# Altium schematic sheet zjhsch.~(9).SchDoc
size A4
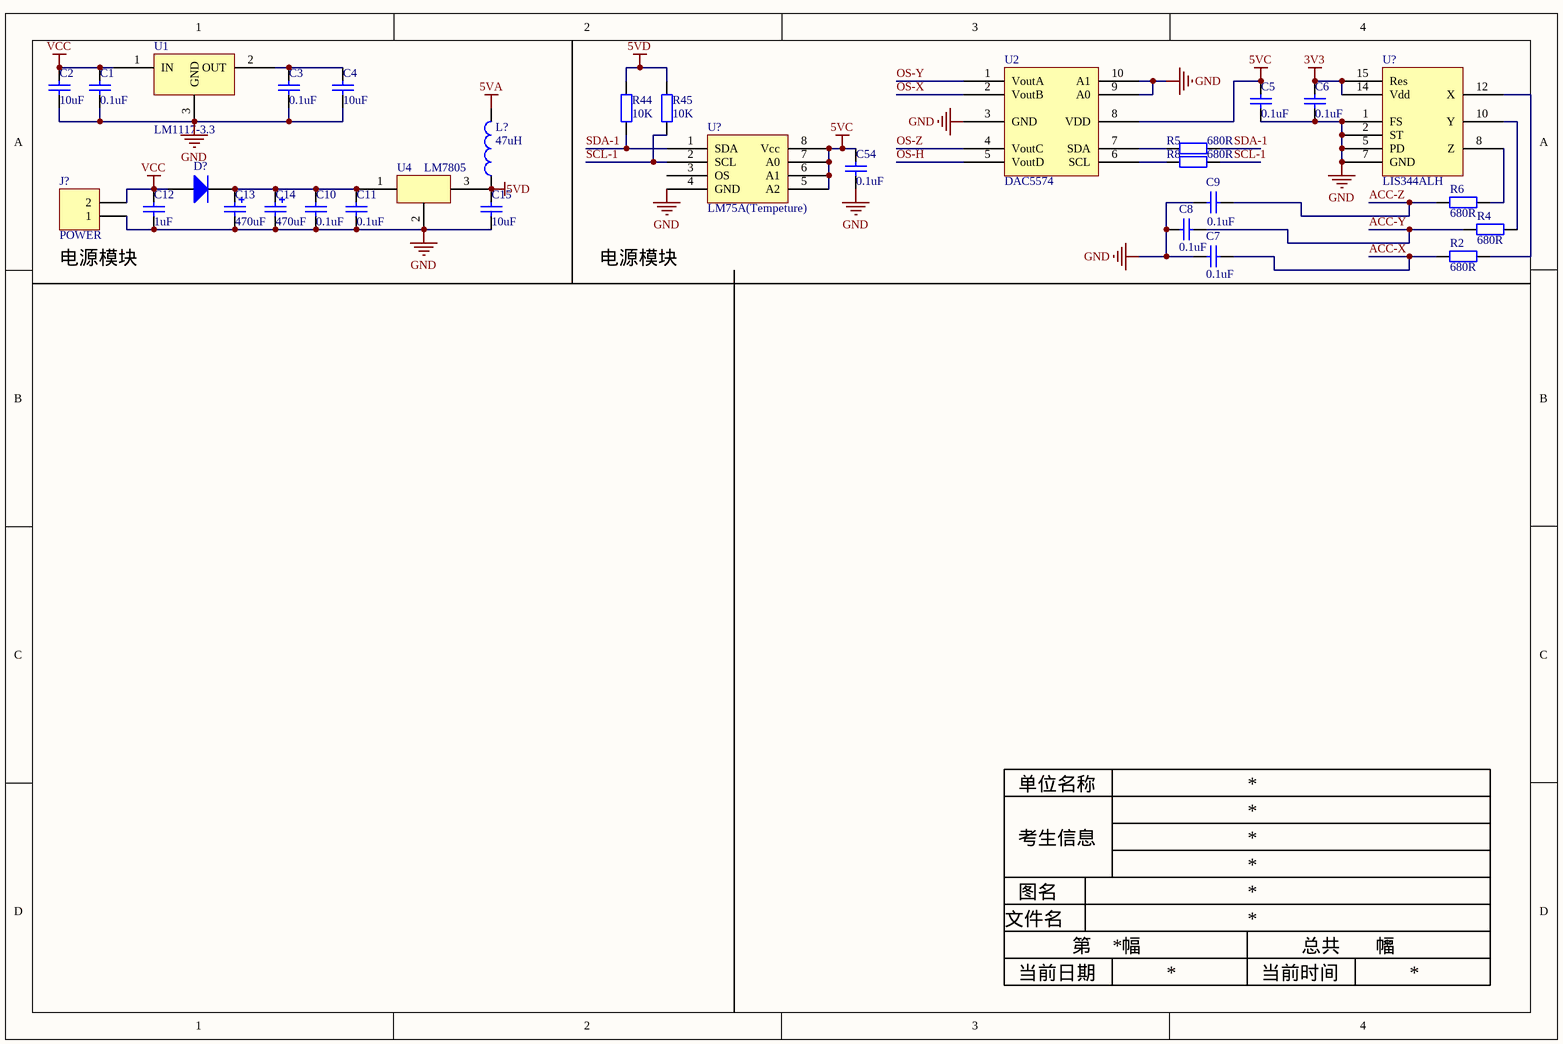
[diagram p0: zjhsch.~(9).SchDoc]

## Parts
(Parts that share a designator on the sheet are numbered #1, #2 ... from top to bottom, then left to right.)
C1  value 0.1uF  [RAD-0.3]  (hidden comment: Cap)
C2  value 10uF  [RAD-0.3]  (hidden comment: Cap)
C3  value 0.1uF  [RAD-0.3]  (hidden comment: Cap)
C4  value 10uF  [RAD-0.3]  (hidden comment: Cap)
C5  value 0.1uF  [RAD-0.3]  (hidden comment: Cap)
C6  value 0.1uF  [RAD-0.3]  (hidden comment: Cap)
C7  value 0.1uF  [RAD-0.3]  (hidden comment: Cap)
C8  value 0.1uF  [RAD-0.3]  (hidden comment: Cap)
C9  value 0.1uF  [RAD-0.3]  (hidden comment: Cap)
C10  value 0.1uF  [RAD-0.3]  (hidden comment: Cap)
C11  value 0.1uF  [RAD-0.3]  (hidden comment: Cap)
C12  value 1uF  [RAD-0.3]  (hidden comment: Cap)
C13  value 470uF  [POLAR0.8]  (hidden comment: Cap Pol2)
C14  value 470uF  [POLAR0.8]  (hidden comment: Cap Pol2)
C15  value 10uF  [RAD-0.3]  (hidden comment: Cap)
C54  value 0.1uF  [RAD-0.3]  (hidden comment: Cap)
D?  Diode  [SMC]  (value not drawn)
J?  POWER  [HDR1X2]
L?  47uH  [DIODE_SMC]
R2  680R  [R0603]
R4  680R  [R0603]
R5  680R  [R0603]
R6  680R  [R0603]
R8  680R  [R0603]
R44  10K  [1608[0603]]
R45  10K  [1608[0603]]
U1  LM1117-3.3  [LM1117-3.3]
U2  DAC5574
U4  LM7805  [TO-220AB]
U?#1  LIS344ALH  [LIS344ALH(Acc)]
U?#2  LM75A(Tempeture)  [LM75A]

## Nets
3V3: C6.2 U?#1.14(Vdd) U?#1.15(Res)
5VA: L?.2
5VC: C5.2 C54.2 U2.8(VDD) U?#2.5(A2) U?#2.6(A1) U?#2.7(A0) U?#2.8(Vcc)
5VD: C15.2 L?.1 R44.2 R45.2 U4.3
GND: C1.1 C2.1 C3.1 C4.1 C5.1 C6.1 C7.2 C8.2 C9.2 C10.1 C11.1 C12.1 C13.2 C14.2 C15.1 C54.1 J?.1 U1.3(GND) U2.3(GND) U2.9(A0) U2.10(A1) U4.2 U?#1.1(FS) U?#1.2(ST) U?#1.5(PD) U?#1.7(GND) U?#2.4(GND)
VCC: C1.2 C2.2 C12.2 D?.1(A) J?.2 U1.1(IN)
ACC-X: C7.1 R2.2
ACC-Y: C8.1 R4.2
ACC-Z: C9.1 R6.2
OS-H: U2.5(VoutD)
OS-X: U2.2(VoutB)
OS-Y: U2.1(VoutA)
OS-Z: U2.4(VoutC)
SCL-1: R8.2 R45.1 U?#2.2(SCL)
SDA-1: R5.2 R44.1 U?#2.1(SDA)
NetC3_2: C3.2 C4.2 U1.2(OUT)
NetC10_2: C10.2 C11.2 C13.1 C14.1 D?.2(K) U4.1
NetR2_1: R2.1 U?#1.12(X)
NetR4_1: R4.1 U?#1.10(Y)
NetR5_1: R5.1 U2.7(SDA)
NetR6_1: R6.1 U?#1.8(Z)
NetR8_1: R8.1 U2.6(SCL)

Not connected (* = marked no-connect by the designer): U?#2 3(OS)

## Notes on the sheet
- 单位名称
- 考生信息
- 文件名
- 图名
- 当前日期
- 第      幅
- 当前时间
- 总共       幅
- Labels drawn without touching a wire or pin: 电源模块

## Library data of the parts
C1-C12 C15 C54 = Cap: Capacitor
C13 C14 = Cap Pol2: Polarized Capacitor (Axial)
D? = Diode: Default Diode
J? = Header 2: Header, 2-Pin
L? = Inductor47uH
R2 R4-R6 R8 = R0603
R44 R45 = R0805
U4 = 7805
U?#1 = ACC(LIS344ALH)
